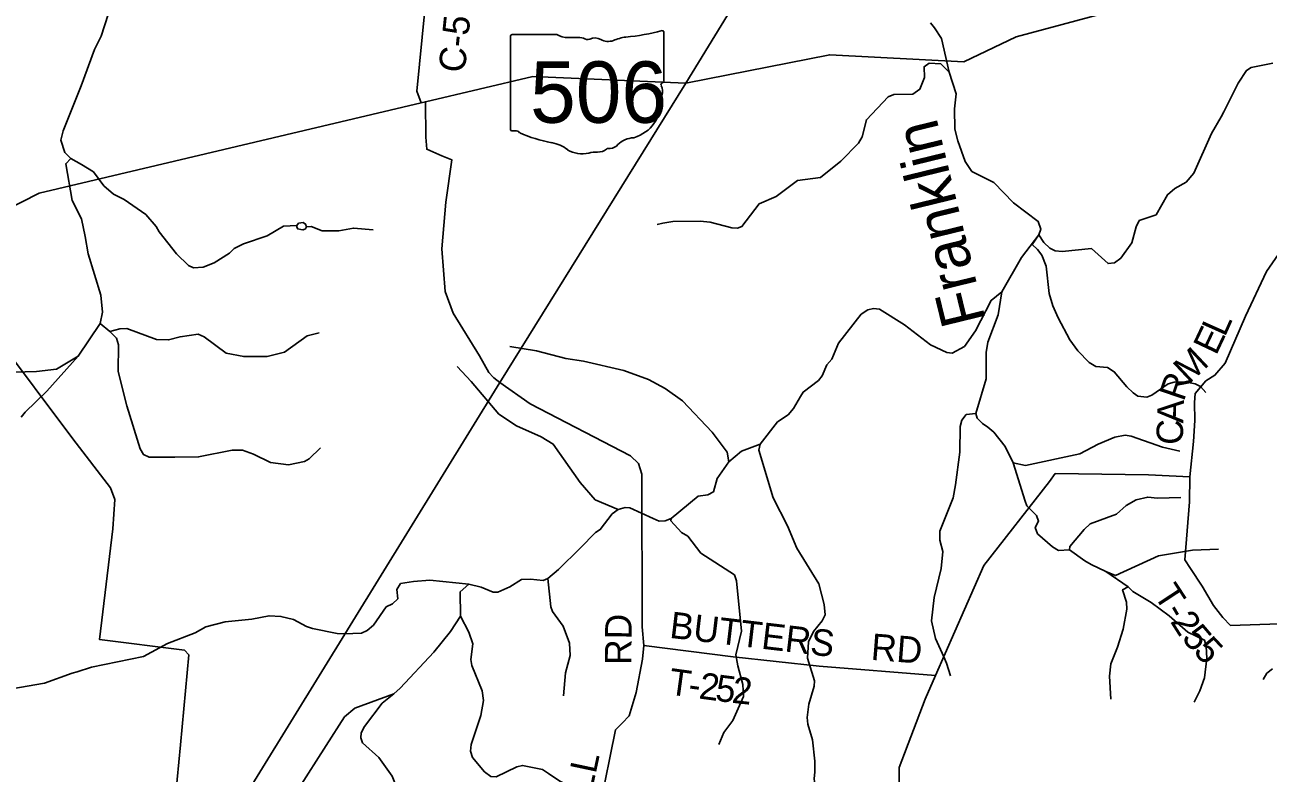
# Model space of a CAD drawing. Extents: x 1525783 to 1900577, y 218250 to 627376.
# Drawn here: x 1693780 to 1707878, y 415754 to 424240 of the extents above; entities that cross this region are included whole.
import ezdxf

# ---------------------------------------------------------------- set-up
doc = ezdxf.new("R2010")
doc.units = 0
for name, color, linetype in [('GM_X_County_Road', 7, 'Continuous'), ('GM_X_County_Road_Text', 7, 'Continuous'), ('GM_X_Minor_Lake', 7, 'Continuous'), ('GM_X_Minor_River', 7, 'Continuous'), ('GM_X_Minor_River_Text', 7, 'Continuous'), ('GM_X_State_Location', 7, 'Continuous'), ('GM_X_State_Route', 7, 'Continuous'), ('GM_X_State_Shield', 7, 'Continuous'), ('GM_X_Township', 7, 'Continuous'), ('GM_X_Township_Road', 7, 'Continuous'), ('GM_X_Township_Road_Text', 7, 'Continuous')]:
    doc.layers.add(name, color=color, linetype=linetype)

msp = doc.modelspace()

# ---------------------------------------------------------------- linework, layer by layer
at = {"layer": 'GM_X_County_Road'}
for points in [[(1698272, 423356), (1698223, 423487), (1698410, 425369), (1698585, 427241), (1698747, 427376), (1699037, 427678), (1699262, 427974), (1699336, 428174), (1699354, 428223), (1699594, 428785), (1699720, 429119), (1699761, 429367), (1699773, 429796), (1699821, 430399), (1699863, 430729), (1699913, 430877), (1700261, 431425), (1700382, 431608), (1700407, 431815)], [(1706990, 419116), (1706990, 419116), (1707032, 419514), (1707048, 419754), (1707041, 419957), (1707049, 420061), (1707171, 420203), (1707274, 420267), (1707390, 420403), (1707621, 420935), (1707859, 421445), (1708063, 421739), (1708212, 421860), (1708359, 421977), (1708441, 422477), (1708466, 422767), (1708581, 422989), (1709232, 423667), (1710297, 424682), (1711087, 425484), (1711108, 425596), (1710849, 425982), (1710748, 426154)], [(1699090, 420244), (1699042, 420298), (1698936, 420486), (1698638, 420970), (1698546, 421215), (1698510, 421702), (1698554, 422229), (1698623, 422709), (1698508, 422756), (1698405, 422801), (1698338, 422830), (1698327, 422967), (1698322, 423368)], [(1695922, 414510), (1695772, 414672), (1695455, 415030), (1695450, 415092), (1695544, 416074), (1695641, 417095), (1695592, 417148), (1694627, 417269), (1694779, 418524), (1694799, 418859), (1694750, 418990), (1694323, 419546), (1692590, 421859)], [(1700299, 415367), (1700476, 416244), (1700552, 416322), (1700632, 416405), (1700712, 416668), (1700784, 417047), (1700799, 417203), (1700778, 417415), (1700776, 419146), (1700740, 419265), (1700648, 419352), (1699510, 419942), (1699164, 420184), (1699097, 420236), (1699090, 420244)], [(1703696, 415457), (1703693, 415819), (1703988, 416592), (1704105, 416860), (1704655, 418110), (1705397, 419061), (1705463, 419154), (1706520, 419137), (1706990, 419116)]]:
    msp.add_lwpolyline(points, dxfattribs=at)
at = {"layer": 'GM_X_Minor_Lake'}
for points in [[(1696863, 421965), (1696865, 421947), (1696875, 421926), (1696908, 421920), (1696934, 421915), (1696961, 421929), (1696973, 421951), (1696964, 421981), (1696934, 421998), (1696908, 421994), (1696882, 421990)], [(1696882, 421990), (1696863, 421965)]]:
    msp.add_lwpolyline(points, dxfattribs=at)
at = {"layer": 'GM_X_Minor_River'}
for points in [[(1694768, 424486), (1694644, 424111), (1694571, 423962), (1694417, 423547), (1694213, 423037), (1694187, 422932), (1694232, 422794), (1694303, 422725), (1694422, 422655), (1694557, 422574), (1694674, 422415), (1694785, 422319), (1694906, 422259), (1695151, 422090), (1695269, 421955), (1695304, 421894), (1695500, 421642), (1695636, 421513), (1695691, 421486), (1695802, 421492), (1695927, 421540), (1696102, 421651), (1696153, 421703), (1696258, 421757), (1696528, 421846), (1696711, 421957), (1696863, 421965)], [(1704050, 424264), (1704095, 424207), (1704173, 424085), (1704260, 423702), (1704339, 423460), (1704320, 423288), (1704326, 423059), (1704359, 422924), (1704443, 422690), (1704517, 422578), (1704698, 422487), (1704767, 422451), (1704992, 422222), (1705272, 422011), (1705301, 421924), (1705279, 421858), (1705080, 421601), (1704858, 421214), (1704817, 420952), (1704701, 420641), (1704681, 420523), (1704679, 420226), (1704565, 419833), (1704579, 419780), (1704640, 419721), (1704701, 419678), (1704768, 419620), (1704897, 419460), (1704988, 419275), (1705122, 418838), (1705143, 418785), (1705253, 418677), (1705274, 418612), (1705237, 418539), (1705263, 418468)], [(1704260, 423702), (1704167, 423798), (1704033, 423807), (1703976, 423765), (1703982, 423643), (1703929, 423511), (1703850, 423453), (1703633, 423449), (1703569, 423424), (1703323, 423165), (1703274, 422969), (1703232, 422898), (1703034, 422693), (1702802, 422510), (1702541, 422475), (1702301, 422295), (1702105, 422212), (1701911, 421955), (1701861, 421935), (1701797, 421937), (1701551, 422001), (1701439, 422015), (1701128, 422011), (1701014, 421991), (1700949, 421978)], [(1705279, 421858), (1705334, 421771), (1705401, 421708), (1705462, 421678), (1705542, 421671), (1705874, 421705), (1706063, 421533), (1706135, 421540), (1706206, 421593), (1706334, 421769), (1706380, 421949), (1706417, 422020), (1706607, 422087), (1706737, 422314), (1706821, 422384), (1706947, 422458), (1707037, 422557), (1707236, 423009), (1707346, 423199), (1707375, 423255), (1707539, 423581), (1707634, 423724), (1707685, 423757), (1707932, 423807)], [(1694303, 422725), (1694244, 422666), (1694318, 422247), (1694421, 422039), (1694465, 421841), (1694499, 421644), (1694641, 421174), (1694661, 420983), (1694635, 420853), (1694383, 420485), (1694029, 420088), (1693784, 419847), (1693739, 419792)], [(1696973, 421951), (1697027, 421952), (1697153, 421903), (1697339, 421906), (1697506, 421935), (1697730, 421917)], [(1705279, 421858), (1705203, 421751), (1705264, 421694), (1705311, 421627), (1705359, 421504), (1705395, 421194), (1705435, 421055), (1705496, 420919), (1705630, 420670), (1705720, 420544), (1705849, 420412), (1705925, 420366), (1706057, 420354), (1706132, 420306), (1706275, 420135), (1706348, 420068), (1706399, 420029), (1706501, 420017), (1706560, 420040), (1706745, 420171), (1706813, 420188), (1706934, 420191), (1707052, 420171), (1707111, 420138), (1707172, 420071)], [(1704858, 421214), (1704738, 421116), (1704561, 420770), (1704433, 420591), (1704294, 420516), (1704234, 420523), (1704049, 420610), (1703755, 420840), (1703471, 421018), (1703403, 421023), (1703337, 421008), (1703264, 420961), (1703007, 420631), (1702929, 420448), (1702874, 420383), (1702819, 420259), (1702778, 420208), (1702607, 420076), (1702574, 420025), (1702496, 419890), (1702434, 419817), (1702316, 419737), (1702119, 419487), (1701905, 419407), (1701763, 419285), (1701629, 419097), (1701590, 418945), (1701525, 418910), (1701416, 418894), (1701107, 418643), (1701042, 418616), (1700974, 418611), (1700905, 418644), (1700640, 418765), (1700586, 418768), (1700509, 418744), (1700438, 418695), (1700305, 418517), (1700252, 418482), (1700078, 418306), (1699831, 418062), (1699709, 417962), (1699656, 417939), (1699512, 417955), (1699410, 417949), (1699278, 417867), (1699143, 417807), (1699090, 417808), (1698953, 417863), (1698814, 417899), (1698371, 417943), (1698187, 417927), (1698040, 417905), (1697996, 417836), (1698008, 417733), (1697947, 417674), (1697878, 417639), (1697734, 417433), (1697663, 417372), (1697596, 417340), (1697400, 417333), (1697323, 417338), (1697040, 417396), (1696972, 417417), (1696827, 417498), (1696684, 417532), (1696549, 417539), (1696352, 417500), (1696051, 417470), (1695831, 417413), (1695712, 417347), (1695397, 417225), (1695125, 417077), (1694536, 416955), (1694372, 416904), (1694318, 416887), (1694003, 416774), (1693367, 416665)], [(1694383, 420485), (1694138, 420337), (1693911, 420311), (1693391, 420296), (1693063, 420292), (1692727, 420456), (1692605, 420477), (1692420, 420452), (1692306, 420442), (1692120, 420477), (1691651, 420692), (1691427, 420728), (1691125, 420756), (1690697, 421034), (1690561, 421081), (1690441, 421093), (1690389, 421090), (1690257, 421074)], [(1694635, 420853), (1694744, 420763), (1694856, 420793), (1694937, 420796), (1695273, 420673), (1695409, 420667), (1695540, 420703), (1695745, 420733), (1695813, 420704), (1696062, 420519), (1696262, 420479), (1696529, 420480), (1696724, 420527), (1696982, 420713), (1697117, 420748)], [(1694744, 420763), (1694820, 420689), (1694843, 420613), (1694839, 420308), (1694938, 419921), (1695089, 419431), (1695126, 419368), (1695188, 419339), (1695481, 419339), (1695749, 419341), (1696130, 419416), (1696246, 419416), (1696373, 419372), (1696564, 419276), (1696768, 419252), (1696949, 419287), (1697004, 419318), (1697133, 419444)], [(1701763, 419285), (1701743, 419394), (1701572, 419621), (1701238, 419975), (1701039, 420117), (1700852, 420218), (1700573, 420319), (1700116, 420426), (1699916, 420456), (1699581, 420542), (1699279, 420591)], [(1700509, 418744), (1700247, 418855), (1700078, 419052), (1699772, 419487), (1699635, 419570), (1699355, 419693), (1699155, 419825), (1698841, 420196), (1698682, 420365)], [(1704565, 419833), (1704455, 419821), (1704406, 419757), (1704386, 419684), (1704383, 419393), (1704332, 419024), (1704307, 418876), (1704155, 418500), (1704155, 418396), (1704189, 418269), (1704169, 418074), (1704091, 417747), (1704060, 417481), (1704106, 417283), (1704201, 417073), (1704229, 417000), (1704277, 416857)], [(1704988, 419275), (1705128, 419245), (1705744, 419374), (1705950, 419485), (1706140, 419566), (1706257, 419586), (1706323, 419577), (1706681, 419452), (1706877, 419406)], [(1702119, 419487), (1702102, 419417), (1702264, 418875), (1702426, 418559), (1702534, 418306), (1702783, 417903), (1702845, 417667), (1702853, 417550), (1702819, 417483), (1702721, 417362), (1702664, 417245), (1702653, 417060), (1702734, 416802), (1702731, 416742), (1702671, 416537), (1702652, 416386), (1702659, 416308), (1702712, 416131), (1702739, 415891), (1702737, 415769), (1702731, 415691), (1702736, 415629)], [(1705625, 418285), (1705630, 418323), (1705790, 418517), (1705861, 418580), (1706158, 418691), (1706268, 418791), (1706383, 418855), (1706512, 418885), (1706624, 418871), (1706889, 418880)], [(1701107, 418643), (1701106, 418617), (1701226, 418482), (1701296, 418441), (1701446, 418250), (1701825, 418002), (1701851, 417935), (1701907, 417365), (1701840, 417097), (1701865, 416972), (1701922, 416761), (1701927, 416624), (1701808, 416351), (1701707, 416217), (1701650, 416079)], [(1705263, 418468), (1705431, 418321), (1705502, 418279), (1705625, 418285), (1705799, 418162), (1705872, 418122), (1706039, 418043), (1706289, 417868), (1706342, 417815), (1706550, 417691), (1706755, 417539), (1706968, 417354), (1707157, 417261), (1707176, 417190), (1707183, 417059), (1707155, 416837), (1707104, 416688), (1707038, 416561)], [(1706039, 418043), (1706147, 417995), (1706634, 418219), (1707022, 418284), (1707315, 418295)], [(1698814, 417899), (1698716, 417809), (1698720, 417534), (1698813, 417354), (1698859, 417221), (1698836, 417042), (1698848, 416974), (1698965, 416689), (1698979, 416580), (1698952, 416408), (1698841, 416079), (1698832, 416003), (1698855, 415933), (1698992, 415768), (1699065, 415716), (1699125, 415713), (1699358, 415827), (1699424, 415842), (1699648, 415794), (1699719, 415751), (1699846, 415662), (1699965, 415602), (1700153, 415574), (1700490, 415458)], [(1699709, 417962), (1699743, 417640), (1699762, 417588), (1699885, 417421), (1699956, 417229), (1699965, 417090), (1699909, 416891), (1699886, 416632)], [(1706289, 417868), (1706228, 417835), (1706273, 417692), (1706276, 417613), (1706233, 417387), (1706171, 417182), (1706094, 416993), (1706079, 416855), (1706094, 416592)], [(1698720, 417534), (1698605, 417360), (1698418, 417126), (1698035, 416718), (1697964, 416653), (1697522, 416490), (1697406, 416392), (1697197, 416069), (1696881, 415575), (1696741, 415391), (1696469, 415171), (1696424, 415120), (1696338, 414935), (1696271, 414685)], [(1707929, 416938), (1707862, 416887), (1707820, 416817)], [(1697964, 416653), (1697832, 416547), (1697630, 416282), (1697595, 416210), (1697588, 416156), (1697607, 416100), (1697794, 415930), (1697945, 415720), (1698019, 415532), (1698025, 415292)]]:
    msp.add_lwpolyline(points, dxfattribs=at)
at = {"layer": 'GM_X_State_Route'}
msp.add_lwpolyline([(1689142, 421080), (1689339, 421062), (1689543, 421042), (1689693, 421028), (1689763, 421029), (1689794, 421044), (1689831, 421194), (1689854, 421228), (1689876, 421244), (1689919, 421275), (1691271, 421563), (1692590, 421859), (1693339, 422026), (1693942, 422331), (1698272, 423356), (1698322, 423368), (1699541, 423656), (1701276, 423581), (1702907, 423901), (1704426, 423822), (1705022, 424106), (1706529, 424509), (1708596, 425070)], dxfattribs=at)
at = {"layer": 'GM_X_State_Shield'}
for p, q in [((1699287, 424112), (1699287, 423055)), ((1699814, 424130), (1699304, 424130)), ((1701027, 423604), (1701027, 424156)), ((1701027, 423604), (1701027, 423604))]:
    msp.add_line(p, q, dxfattribs=at)
for centre, major_axis, start_param, end_param in [((1699307, 424114), (20.2, 0), 1.712693, 3.28349), ((1699935, 424253), (196, 0), 4.042523, 4.731795), ((1700000, 423537), (702, 0), 1.404758, 1.657858), ((1700159, 424120), (56.4, 0), 3.836095, 5.185415), ((1700242, 423998), (117, 0), 0.950623, 2.079405), ((1700394, 424165), (141, 0), 4.081561, 5.145723), ((1700643, 423807), (371, 0), 1.699011, 2.107814), ((1700407, 425571), (1845, 0), 4.814394, 5.042369), ((1701008, 424159), (19.4, 0), 6.141152, 7.989035), ((1701023, 423563), (30, 0), 1.883978, 3.671073), ((1700832, 423493), (180, 0), 5.934695, 6.695948), ((1701007, 423601), (20.7, 0), 5.05454, 6.418171), ((1700511, 423302), (462, 0), 5.101752, 6.440018), ((1701097, 423372), (131, 0), 2.387724, 3.262537), ((1699307, 423053), (20.3, 0), 3.00124, 4.508301), ((1699310, 423161), (155, 0), 4.665946, 4.897461), ((1699342, 422994), (56, 0), 0.519207, 1.627899), ((1700049, 423944), (1333, 0), 4.195997, 4.488961), ((1700705, 422759), (253, 0), 1.647645, 2.488434), ((1699651, 422581), (417, 0), 0.823519, 1.323587), ((1700102, 422989), (265, 0), 4.026481, 4.996735), ((1700255, 422624), (217, 0), 1.495662, 1.94098), ((1700275, 422910), (141, 0), 4.691044, 5.507374), ((1700402, 422808), (39.7, 0), 1.147584, 2.315152), ((1700385, 422953), (149, 0), 4.937069, 5.64225)]:
    msp.add_ellipse(centre, major_axis=major_axis, ratio=0.8, start_param=start_param, end_param=end_param, dxfattribs=at)
at = {"layer": 'GM_X_Township'}
for points in [[(1695772, 414672), (1699164, 420184), (1701276, 423581), (1704308, 428530)], [(1704308, 428530), (1701276, 423581), (1699164, 420184), (1695772, 414672)]]:
    msp.add_lwpolyline(points, dxfattribs=at)
at = {"layer": 'GM_X_Township_Road'}
for points in [[(1706990, 419116), (1706988, 418831), (1706932, 418172), (1706998, 418076), (1707131, 417876), (1707258, 417656), (1707365, 417520), (1707451, 417429), (1708229, 417455)], [(1700799, 417203), (1701811, 417074), (1702787, 416966), (1704105, 416860)]]:
    msp.add_lwpolyline(points, dxfattribs=at)

# ---------------------------------------------------------------- texts
at = {"layer": 'GM_X_County_Road_Text'}
for s, rotation, p in [('C-51', 84.1868, (1698768, 423690)), ('E', 64.6654, (1707288, 420483)), ('L', 65.9185, (1707387, 420692)), ('M', 43.2433, (1706980, 420161)), ('R', 71.117, (1706920, 419960)), ('A', 88.0434, (1706916, 419719)), ('C', 88.4504, (1706909, 419474)), ('RD', 89.5867, (1700657, 416981)), ('HILL', 78.008, (1700123, 415129))]:
    msp.add_text(s, height=300, rotation=rotation, dxfattribs=at).set_placement(p)
at = {"layer": 'GM_X_Minor_River_Text'}
msp.add_text('Franklin', height=500.1, rotation=103.7234, dxfattribs=at).set_placement((1704678, 420888))
at = {"layer": 'GM_X_State_Location'}
for s in ['s', 'r']:
    msp.add_text(s, height=1, dxfattribs=at).set_placement((1700138, 423513))
msp.add_text('506', height=1, rotation=0, dxfattribs=at).set_placement((1699785, 423441))
at = {"layer": 'GM_X_State_Shield'}
msp.add_text('506', height=696.1, dxfattribs=at).set_placement((1699509, 423130))
at = {"layer": 'GM_X_Township_Road_Text'}
for s, rotation, p in [('T', 303.2729, (1706573, 417776)), ('BUTTERS', 353.2548, (1701082, 417290)), ('2', 302.4529, (1706762, 417474)), ('-', 300.0092, (1706694, 417593)), ('5', 310.3693, (1706888, 417282)), ('RD', 355.564, (1703367, 417040)), ('5', 313.1416, (1707019, 417129)), ('T', 352.1887, (1701069, 416649)), ('2', 352.3754, (1701414, 416602)), ('-', 352.2312, (1701292, 416618)), ('5', 352.764, (1701600, 416577)), ('2', 353.8707, (1701789, 416553))]:
    msp.add_text(s, height=300, rotation=rotation, dxfattribs=at).set_placement(p)

doc.saveas('drawing.dxf')
